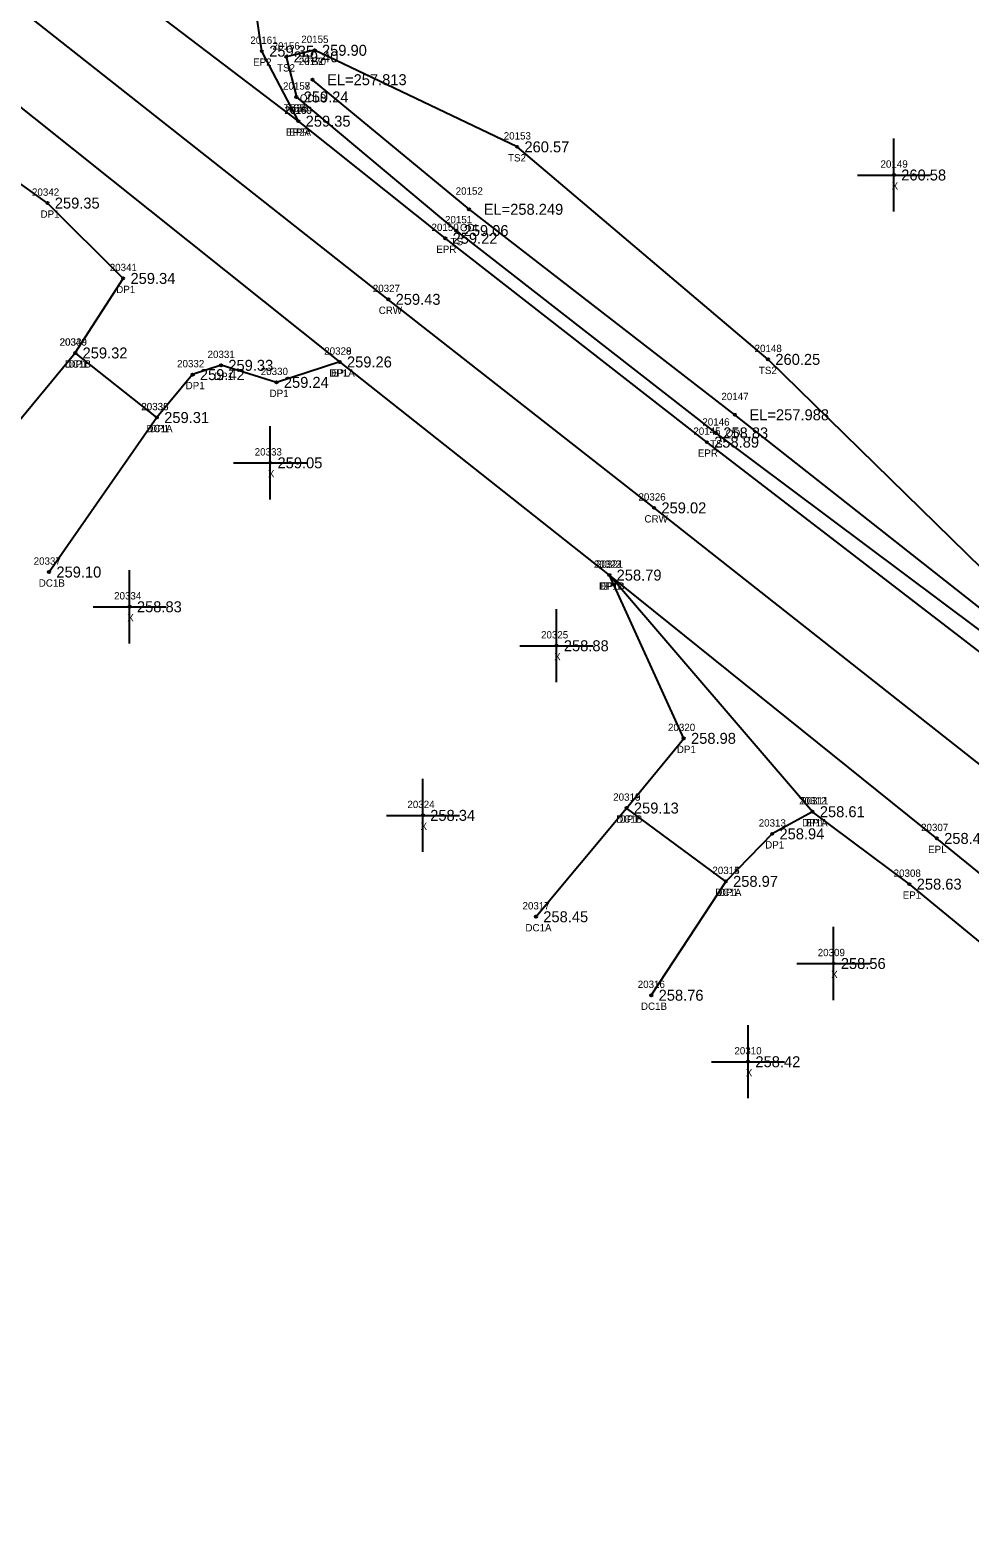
# Model space of a CAD drawing. Extents: x 1961330 to 1962287, y 800294 to 801079.
# Drawn here: x 1961759.1 to 1961887.6, y 800521.8 to 800727.9 of the extents above; entities that cross this region are included whole.
import ezdxf

# ---------------------------------------------------------------- set-up
doc = ezdxf.new("R2010")
doc.units = 0
for name, color, linetype in [('RD_DTM_BkLn1', 7, 'Continuous'), ('RD_DTM_BkLn2', 7, 'Continuous'), ('RD_DTM_BkLn_txCode', 7, 'Continuous'), ('RD_EX_Conc', 7, 'Continuous'), ('RD_EX_Conc_txCode', 7, 'Continuous'), ('RD_EX_Driveway', 7, 'Continuous'), ('RD_EX_Driveway_txCode', 7, 'Continuous'), ('RD_EX_H2O', 7, 'Continuous'), ('RD_EX_H2O_txCode', 7, 'Continuous'), ('RD_EX_Misc', 7, 'Continuous'), ('RD_EX_Misc_txCode', 7, 'Continuous'), ('RD_EX_Road', 7, 'Continuous'), ('RD_EX_Road_txCode', 7, 'Continuous'), ('RD_EX_TX_Conc_ELEV', 7, 'Continuous'), ('RD_EX_TX_Driveway_ELEV', 7, 'Continuous'), ('RD_EX_TX_H2O_ELEV', 7, 'Continuous'), ('RD_EX_TX_Misc_ELEV', 7, 'Continuous'), ('RD_EX_TX_Road_ELEV', 7, 'Continuous'), ('RD_HC_Survey_ELEV', 7, 'Continuous'), ('RD_HC_Survey_txCode', 7, 'Continuous'), ('RD_SMD_Locator', 7, 'Continuous')]:
    doc.layers.add(name, color=color, linetype=linetype)

msp = doc.modelspace()

# ---------------------------------------------------------------- linework, layer by layer
at = {"layer": 'RD_DTM_BkLn1'}
msp.add_lwpolyline([(1962257.08, 800334.72), (1962203.79, 800372.43), (1962164.31, 800399.58), (1962126.58, 800429.85), (1962084.5, 800463.37), (1962045.12, 800502.48), (1962010.49, 800530.36), (1961971.27, 800562.01), (1961931.18, 800594.14), (1961890.91, 800625.98), (1961844.41, 800662.62), (1961808.07, 800691.13), (1961729.11, 800753.37), (1961696.19, 800780.32), (1961667.25, 800802.66), (1961624.93, 800836.78), (1961588.01, 800866), (1961545.37, 800899.49), (1961472.25, 800957.29), (1961437.91, 800983.99), (1961399.03, 801013.16), (1961365.01, 801035.89)], dxfattribs=at)
at = {"layer": 'RD_DTM_BkLn2'}
for points in [[(1961901.85, 800638.69), (1961901.82, 800642.02), (1961859.99, 800682.92), (1961825.68, 800711.98), (1961798, 800725.18), (1961794.11, 800724.28), (1961795.5, 800718.8)], [(1961901.85, 800638.69), (1961899.11, 800638.31), (1961852.87, 800672.87), (1961817.37, 800700.53), (1961795.5, 800718.8)]]:
    msp.add_lwpolyline(points, dxfattribs=at)
at = {"layer": 'RD_EX_Conc'}
for p, q in [((1961745.74, 800660.3), (1961765.27, 800683.8)), ((1961776.43, 800674.97), (1961761.69, 800653.85)), ((1961828.26, 800606.72), (1961840.65, 800621.58)), ((1961854.21, 800611.56), (1961844.03, 800595.99))]:
    msp.add_line(p, q, dxfattribs=at)
at = {"layer": 'RD_EX_Driveway'}
for points in [[(1961801.42, 800682.57), (1961792.79, 800679.78), (1961785.2, 800682.11), (1961781.31, 800680.84), (1961776.43, 800674.97), (1961765.27, 800683.8), (1961771.82, 800693.99), (1961761.47, 800704.29), (1961751.75, 800711.21), (1961746.29, 800707.66), (1961742.29, 800702.88), (1961731.89, 800711.6), (1961735.94, 800718.16), (1961732.79, 800728.82), (1961728.41, 800740.86)], [(1961866.07, 800621.08), (1961860.55, 800618.05), (1961854.21, 800611.56), (1961840.65, 800621.58), (1961848.46, 800631.11), (1961838.29, 800653.43)]]:
    msp.add_lwpolyline(points, dxfattribs=at)
at = {"layer": 'RD_EX_H2O'}
msp.add_lwpolyline([(1961899.52, 800640.6), (1961855.45, 800675.35), (1961819.11, 800703.44), (1961797.7, 800721.16)], dxfattribs=at)
at = {"layer": 'RD_EX_Misc'}
for p, q in [((1961877.2, 800703.13), (1961877.2, 800713.13)), ((1961872.2, 800708.13), (1961882.2, 800708.13)), ((1961791.92, 800663.78), (1961791.92, 800673.78)), ((1961786.92, 800668.78), (1961796.92, 800668.78)), ((1961772.7, 800644.1), (1961772.7, 800654.1)), ((1961767.7, 800649.1), (1961777.7, 800649.1)), ((1961831.07, 800638.77), (1961831.07, 800648.77)), ((1961826.07, 800643.77), (1961836.07, 800643.77)), ((1961812.8, 800615.58), (1961812.8, 800625.58)), ((1961807.8, 800620.58), (1961817.8, 800620.58)), ((1961868.94, 800595.33), (1961868.94, 800605.33)), ((1961863.94, 800600.33), (1961873.94, 800600.33)), ((1961857.26, 800581.9), (1961857.26, 800591.9)), ((1961852.26, 800586.9), (1961862.26, 800586.9))]:
    msp.add_line(p, q, dxfattribs=at)
at = {"layer": 'RD_EX_Road'}
for points in [[(1962276.74, 800366.53), (1962275.76, 800367.28), (1962226.46, 800400.66), (1962183.05, 800429.73), (1962145.98, 800455.38), (1962104.4, 800484.06), (1962056.77, 800517.94), (1962023.95, 800541.05), (1961991.87, 800563.56), (1961983.89, 800569.94), (1961938.77, 800603.67), (1961913.43, 800623.83), (1961897.73, 800636.17), (1961851.62, 800671.61), (1961815.86, 800699.48), (1961795.77, 800715.49), (1961771.88, 800733.73), (1961750.77, 800750.96), (1961735.63, 800762.82), (1961702.92, 800788.52), (1961676.16, 800810.27), (1961651.45, 800830.73), (1961641.14, 800839.02)], [(1962241.79, 800315.68), (1962238.35, 800317.6), (1962189.92, 800352.69), (1962151.64, 800383.49), (1962113.78, 800416.39), (1962074.11, 800451.29), (1962034.78, 800486.96), (1962017.07, 800503.17), (1961999.46, 800519.25), (1961962.48, 800552.12), (1961937.08, 800573.11), (1961923.19, 800584.9), (1961883.07, 800617.43), (1961838.29, 800653.43), (1961801.42, 800682.57), (1961728.41, 800740.86), (1961722.95, 800745.11), (1961689.13, 800771.93), (1961670.14, 800787.03), (1961660.52, 800795.31), (1961637.49, 800813.67)], [(1961795.77, 800715.49), (1961790.78, 800725.06), (1961789.09, 800736.73), (1961791.99, 800743.29), (1961791.54, 800743.77), (1961790.92, 800744.13), (1961808.7, 800765.82)], [(1961992.53, 800418.34), (1962000.94, 800437), (1962011.01, 800464.81), (1962016.84, 800481.64), (1962015.31, 800499.65), (1961996.99, 800516.71), (1961979.47, 800530.76), (1961969.8, 800538.75), (1961958.28, 800547.16), (1961941.07, 800560.82), (1961925.41, 800573.41), (1961918.19, 800579.25), (1961879.32, 800611.18), (1961866.07, 800621.08), (1961838.29, 800653.43)]]:
    msp.add_lwpolyline(points, dxfattribs=at)
at = {"layer": 'RD_SMD_Locator'}
for centre in [(1961790.78, 800725.06), (1961794.11, 800724.28), (1961798, 800725.18), (1961797.7, 800721.16), (1961795.5, 800718.8), (1961795.5, 800718.8), (1961795.77, 800715.49), (1961795.77, 800715.49), (1961825.68, 800711.98), (1961877.2, 800708.13), (1961761.47, 800704.29), (1961819.11, 800703.44), (1961815.86, 800699.48), (1961817.37, 800700.53), (1961771.82, 800693.99), (1961808.07, 800691.13), (1961765.27, 800683.8), (1961765.27, 800683.8), (1961785.2, 800682.11), (1961801.42, 800682.57), (1961801.42, 800682.57), (1961859.99, 800682.92), (1961781.31, 800680.84), (1961792.79, 800679.78), (1961776.43, 800674.97), (1961776.43, 800674.97), (1961855.45, 800675.35), (1961852.87, 800672.87), (1961851.62, 800671.61), (1961791.92, 800668.78), (1961844.41, 800662.62), (1961761.69, 800653.85), (1961838.29, 800653.43), (1961838.29, 800653.43), (1961838.29, 800653.43), (1961772.7, 800649.1), (1961831.07, 800643.77), (1961848.46, 800631.11), (1961840.65, 800621.58), (1961840.65, 800621.58), (1961812.8, 800620.58), (1961866.07, 800621.08), (1961866.07, 800621.08), (1961860.55, 800618.05), (1961883.07, 800617.43), (1961854.21, 800611.56), (1961854.21, 800611.56), (1961879.32, 800611.18), (1961828.26, 800606.72), (1961868.94, 800600.33), (1961844.03, 800595.99), (1961857.26, 800586.9)]:
    msp.add_circle(centre, 0.15, dxfattribs=at)

# ---------------------------------------------------------------- texts
at = {"layer": 'RD_DTM_BkLn_txCode'}
for s, p in [('20155', (1961796.17, 800726.18)), ('20156', (1961792.25, 800725.28)), ('TS2', (1961792.86, 800722.28)), ('TS2', (1961796.76, 800723.18)), ('20157', (1961793.67, 800719.8)), ('20158', (1961793.67, 800719.8)), ('TS2B', (1961793.78, 800716.8)), ('TSB', (1961794.23, 800716.8)), ('20153', (1961823.85, 800712.98)), ('TS2', (1961824.44, 800709.98)), ('20151', (1961815.82, 800701.53)), ('TS', (1961816.58, 800698.53)), ('20148', (1961858.15, 800683.92)), ('TS2', (1961858.74, 800680.92)), ('20146', (1961851.01, 800673.87)), ('TS', (1961852.07, 800670.87))]:
    msp.add_text(s, height=1, dxfattribs=at).set_placement(p)
at = {"layer": 'RD_EX_Conc_txCode'}
for s, p in [('20339', (1961763.15, 800684.8)), ('DC1B', (1961763.85, 800681.8)), ('20336', (1961774.29, 800675.97)), ('DC1A', (1961775, 800672.97)), ('20337', (1961759.58, 800654.85)), ('DC1B', (1961760.28, 800651.85)), ('20318', (1961838.82, 800622.58)), ('DC1B', (1961839.24, 800619.58)), ('20315', (1961852.38, 800612.56)), ('DC1A', (1961852.78, 800609.56)), ('20317', (1961826.42, 800607.72)), ('DC1A', (1961826.82, 800604.72)), ('20316', (1961842.17, 800596.99)), ('DC1B', (1961842.61, 800593.99))]:
    msp.add_text(s, height=1, dxfattribs=at).set_placement(p)
at = {"layer": 'RD_EX_Driveway_txCode'}
for s, p in [('20342', (1961759.35, 800705.29)), ('DP1', (1961760.52, 800702.29)), ('20341', (1961769.98, 800694.99)), ('DP1', (1961770.87, 800691.99)), ('20340', (1961763.11, 800684.8)), ('20331', (1961783.36, 800683.11)), ('20329', (1961799.31, 800683.57)), ('DP1', (1961764.33, 800681.8)), ('20332', (1961779.19, 800681.84)), ('DP1', (1961784.25, 800680.11)), ('20330', (1961790.63, 800680.78)), ('DP1A', (1961799.99, 800680.57)), ('DP1', (1961780.36, 800678.84)), ('20335', (1961774.31, 800675.97)), ('DP1', (1961791.84, 800677.78)), ('DP1', (1961775.49, 800672.97)), ('20321', (1961836.46, 800654.43)), ('DP1B', (1961836.88, 800651.43)), ('20320', (1961846.31, 800632.11)), ('DP1', (1961847.52, 800629.11)), ('20319', (1961838.82, 800622.58)), ('20312', (1961864.24, 800622.08)), ('DP1', (1961839.71, 800619.58)), ('20313', (1961858.71, 800619.05)), ('DP1A', (1961864.64, 800619.08)), ('DP1', (1961859.6, 800616.05)), ('20314', (1961852.38, 800612.56)), ('DP1', (1961853.27, 800609.56))]:
    msp.add_text(s, height=1, dxfattribs=at).set_placement(p)
at = {"layer": 'RD_EX_H2O_txCode'}
for s, p in [('20170', (1961795.83, 800723.16)), ('ODLB', (1961795.98, 800718.16)), ('20152', (1961817.28, 800705.44)), ('ODL', (1961817.87, 800700.44)), ('20147', (1961853.61, 800677.35)), ('ODL', (1961854.2, 800672.35))]:
    msp.add_text(s, height=1, dxfattribs=at).set_placement(p)
at = {"layer": 'RD_EX_Misc_txCode'}
for s, p in [('20149', (1961875.37, 800709.13)), ('X', (1961876.89, 800706.13)), ('20333', (1961789.8, 800669.78)), ('X', (1961791.61, 800666.78)), ('20334', (1961770.58, 800650.1)), ('X', (1961772.38, 800647.1)), ('20325', (1961828.95, 800644.77)), ('X', (1961830.75, 800641.77)), ('20324', (1961810.68, 800621.58)), ('X', (1961812.48, 800618.58)), ('20309', (1961866.78, 800601.33)), ('X', (1961868.62, 800598.33)), ('20310', (1961855.39, 800587.9)), ('X', (1961856.95, 800584.9))]:
    msp.add_text(s, height=1, dxfattribs=at).set_placement(p)
at = {"layer": 'RD_EX_Road_txCode'}
for s, p in [('20161', (1961789.21, 800726.06)), ('EP2', (1961789.58, 800723.06)), ('20160', (1961793.87, 800716.49)), ('20159', (1961793.94, 800716.49)), ('EP2A', (1961794.08, 800713.49)), ('EPR', (1961794.54, 800713.49)), ('20150', (1961813.98, 800700.48)), ('EPR', (1961814.63, 800697.48)), ('20328', (1961799.31, 800683.57)), ('EPL', (1961800.22, 800680.57)), ('20145', (1961849.78, 800672.61)), ('EPR', (1961850.39, 800669.61)), ('20322', (1961836.18, 800654.43)), ('20323', (1961836.18, 800654.43)), ('EP1B', (1961836.9, 800651.43)), ('EPL', (1961837.09, 800651.43)), ('20311', (1961864.52, 800622.08)), ('EP1', (1961865.15, 800619.08)), ('20307', (1961880.91, 800618.43)), ('EPL', (1961881.87, 800615.43)), ('20308', (1961877.16, 800612.18)), ('EP1', (1961878.4, 800609.18))]:
    msp.add_text(s, height=1, dxfattribs=at).set_placement(p)
at = {"layer": 'RD_EX_TX_Conc_ELEV'}
for s, p in [('259.32', (1961766.27, 800683.05)), ('259.31', (1961777.43, 800674.22)), ('259.10', (1961762.69, 800653.1)), ('259.13', (1961841.65, 800620.83)), ('258.97', (1961855.21, 800610.81)), ('258.45', (1961829.26, 800605.97)), ('258.76', (1961845.03, 800595.24))]:
    msp.add_text(s, height=1.5, dxfattribs=at).set_placement(p)
at = {"layer": 'RD_EX_TX_Driveway_ELEV'}
for s, p in [('259.35', (1961762.47, 800703.54)), ('259.34', (1961772.82, 800693.24)), ('259.32', (1961766.27, 800683.05)), ('259.26', (1961802.42, 800681.82)), ('259.42', (1961782.31, 800680.09)), ('259.33', (1961786.2, 800681.36)), ('259.24', (1961793.79, 800679.03)), ('259.31', (1961777.43, 800674.22)), ('258.79', (1961839.29, 800652.68)), ('258.98', (1961849.46, 800630.36)), ('259.13', (1961841.65, 800620.83)), ('258.61', (1961867.07, 800620.33)), ('258.94', (1961861.55, 800617.3)), ('258.97', (1961855.21, 800610.81))]:
    msp.add_text(s, height=1.5, dxfattribs=at).set_placement(p)
at = {"layer": 'RD_EX_TX_H2O_ELEV'}
for s, p in [('EL=257.813', (1961799.7, 800720.41)), ('EL=258.249', (1961821.11, 800702.69)), ('EL=257.988', (1961857.45, 800674.6))]:
    msp.add_text(s, height=1.5, dxfattribs=at).set_placement(p)
at = {"layer": 'RD_EX_TX_Misc_ELEV'}
for s, p in [('259.40', (1961795.11, 800723.53)), ('259.90', (1961799, 800724.43)), ('259.24', (1961796.5, 800718.05)), ('259.24', (1961796.5, 800718.05)), ('260.57', (1961826.68, 800711.23)), ('260.58', (1961878.2, 800707.38)), ('259.06', (1961818.37, 800699.78)), ('260.25', (1961860.99, 800682.17)), ('258.83', (1961853.87, 800672.12)), ('259.05', (1961792.92, 800668.03)), ('258.83', (1961773.7, 800648.35)), ('258.88', (1961832.07, 800643.02)), ('258.34', (1961813.8, 800619.83)), ('258.56', (1961869.94, 800599.58)), ('258.42', (1961858.26, 800586.15))]:
    msp.add_text(s, height=1.5, dxfattribs=at).set_placement(p)
at = {"layer": 'RD_EX_TX_Road_ELEV'}
for s, p in [('259.35', (1961791.78, 800724.31)), ('259.35', (1961796.77, 800714.74)), ('259.35', (1961796.77, 800714.74)), ('259.22', (1961816.86, 800698.73)), ('259.26', (1961802.42, 800681.82)), ('258.89', (1961852.62, 800670.86)), ('258.79', (1961839.29, 800652.68)), ('258.79', (1961839.29, 800652.68)), ('258.61', (1961867.07, 800620.33)), ('258.45', (1961884.07, 800616.68)), ('258.63', (1961880.32, 800610.43))]:
    msp.add_text(s, height=1.5, dxfattribs=at).set_placement(p)
at = {"layer": 'RD_HC_Survey_ELEV'}
for s, p in [('259.43', (1961809.07, 800690.38)), ('259.02', (1961845.41, 800661.87))]:
    msp.add_text(s, height=1.5, dxfattribs=at).set_placement(p)
at = {"layer": 'RD_HC_Survey_txCode'}
for s, p in [('20327', (1961805.95, 800692.13)), ('CRW', (1961806.76, 800689.13)), ('20326', (1961842.27, 800663.62)), ('CRW', (1961843.09, 800660.62))]:
    msp.add_text(s, height=1, dxfattribs=at).set_placement(p)

doc.saveas('drawing.dxf')
